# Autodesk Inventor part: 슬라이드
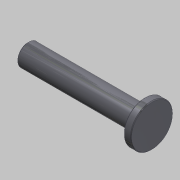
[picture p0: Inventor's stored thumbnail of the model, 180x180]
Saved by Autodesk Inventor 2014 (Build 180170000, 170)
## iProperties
Created: 2015-10
Part Number: 슬라이드
Document SubType Name: Modeling
Designer: mdu
Density: 7.86 g/cm^3
Material: 강철, 연강
Appearance: 강철 - 광택
Mass: 1065.95 g
Surface Area: 229.101 cm^2
Volume: 135.617 cm^3
Author: mdu
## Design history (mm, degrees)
sketch "스케치1"
  geometry: L1 (-75, 162)-(-75, 58) reference; L2 (-148, 110)-(22, 110); L3 (-148, 110)-(-148, 125); L4 (-148, 125)-(12, 125); L5 (12, 125)-(12, 139); L6 (12, 139)-(22, 139); L7 (22, 139)-(22, 110); 2 further points
  constraints: 12 end point, 3 parallel, 3 perpendicular, 1 midpoint, 1 point on line
  dimensions: "d0" = 58 diameter of L6 L2; "d1" = 30 diameter of L4 L2; "d2" = 10 distance of L5.end L6.end; "d3" = 170 distance of L2.start L2.end; "d4" = 73 distance between parallel lines of L3 L1
revolve "회전1" sketch "스케치1" stored, may be unused: angle "d5" = 90 deg
hole "구멍1" diameter "d11" = 13.376; stored, may be unused: countersink angle "d15" = 90 deg, drill point angle "d17" = 118 deg; dims "d9" = 10, "d10" = 10, "d12" = 22, "d13" = 4, "d14" = 2, "d16" = 25
chamfer "모따기1" distance "d6" = 1; stored, may be unused: second distance "d7" = 2, angle "d8" = 45 deg
node "솔리드1"
node "참조1"
